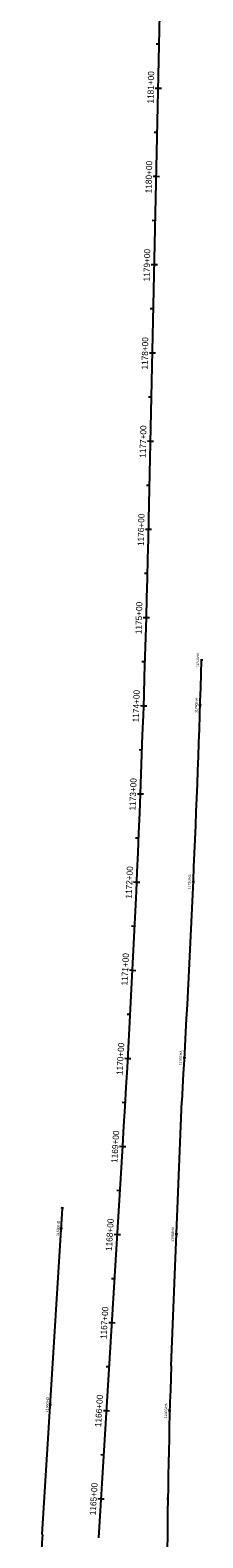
# Model space of a CAD drawing. Extents: x 596008 to 607538, y 326212 to 405053.
# Drawn here: x 604113 to 604309, y 341268 to 342976 of the extents above; entities that cross this region are included whole.
import ezdxf

# ---------------------------------------------------------------- set-up
doc = ezdxf.new("R2010")
doc.units = 0
for name, color, linetype in [('P_ALI_200', 7, 'Continuous'), ('P_ALI_200_Sta', 7, 'Continuous'), ('P_ALI_200_Tic', 7, 'Continuous')]:
    doc.layers.add(name, color=color, linetype=linetype)

msp = doc.modelspace()

# ---------------------------------------------------------------- linework, layer by layer
at = {"layer": 'P_ALI_200'}
for points in [[(604247.6, 342421.3), (604296.1, 344641.5)], [(604272.9, 341462.5), (604285.2, 341762.3)], [(604190.8, 341267.5), (604218.1, 341711.8)], [(604126.9, 341271.4), (604149.6, 341641.2)]]:
    msp.add_lwpolyline(points, dxfattribs=at)
for centre, radius, start, end in [((586251.9, 342814.3), 18000, 356.48854, 358.74902), ((586251.9, 342814.3), 18064, 356.66136, 358.24837), ((612353.2, 341187.1), 8085, 178.04799, 179.61083), ((614687.1, 340623.4), 10580, 176.48854, 178.06311)]:
    msp.add_arc(centre, radius, start, end, dxfattribs=at)
at = {"layer": 'P_ALI_200_Sta'}
for points in [[(604259.3, 342959.9), (604255.8, 342960)], [(604258.3, 342909.9), (604254.8, 342910)], [(604258.3, 342909.9), (604258.3, 342909.9)], [(604261.8, 342909.9), (604258.3, 342909.9)], [(604257.2, 342859.9), (604253.7, 342860)], [(604256.1, 342810), (604252.6, 342810)], [(604256.1, 342810), (604256.1, 342810)], [(604259.6, 342809.9), (604256.1, 342810)], [(604255, 342760), (604251.5, 342760.1)], [(604253.9, 342710), (604250.4, 342710.1)], [(604253.9, 342710), (604253.9, 342710)], [(604257.4, 342709.9), (604253.9, 342710)], [(604252.8, 342660), (604249.3, 342660.1)], [(604251.7, 342610), (604248.2, 342610.1)], [(604251.7, 342610), (604251.7, 342610)], [(604255.2, 342609.9), (604251.7, 342610)], [(604250.6, 342560), (604247.1, 342560.1)], [(604249.5, 342510), (604246, 342510.1)], [(604249.5, 342510), (604249.5, 342510)], [(604253, 342510), (604249.5, 342510)], [(604248.4, 342460), (604244.9, 342460.1)], [(604247.3, 342410.1), (604243.8, 342410.1)], [(604247.3, 342410.1), (604247.3, 342410.1)], [(604250.8, 342410), (604247.3, 342410.1)], [(604246.1, 342360.1), (604242.6, 342360.2)], [(604244.8, 342310.1), (604241.3, 342310.2)], [(604244.8, 342310.1), (604244.8, 342310.1)], [(604248.3, 342310), (604244.8, 342310.1)], [(604243.3, 342260.1), (604239.8, 342260.2)], [(604307.4, 342262.2), (604306, 342262.2)], [(604307.4, 342262.2), (604307.4, 342262.2)], [(604308.8, 342262.1), (604307.4, 342262.2)], [(604241.7, 342210.1), (604238.2, 342210.3)], [(604241.7, 342210.1), (604241.7, 342210.1)], [(604245.2, 342210), (604241.7, 342210.1)], [(604305.8, 342210.9), (604304.4, 342210.9)], [(604305.8, 342210.9), (604305.8, 342210.9)], [(604307.2, 342210.8), (604305.8, 342210.9)], [(604240, 342160.2), (604236.5, 342160.3)], [(604238.1, 342110.2), (604234.6, 342110.3)], [(604238.1, 342110.2), (604238.1, 342110.2)], [(604241.6, 342110.1), (604238.1, 342110.2)], [(604236.1, 342060.2), (604232.6, 342060.4)], [(604233.9, 342010.3), (604230.4, 342010.4)], [(604233.9, 342010.3), (604233.9, 342010.3)], [(604237.4, 342010.1), (604233.9, 342010.3)], [(604298, 342011), (604296.6, 342011.1)], [(604298, 342011), (604298, 342011)], [(604299.4, 342011), (604298, 342011)], [(604231.6, 341960.3), (604228.1, 341960.5)], [(604229.2, 341910.4), (604225.7, 341910.6)], [(604229.2, 341910.4), (604229.2, 341910.4)], [(604232.7, 341910.2), (604229.2, 341910.4)], [(604226.6, 341860.5), (604223.1, 341860.7)], [(604223.9, 341810.5), (604220.4, 341810.7)], [(604223.9, 341810.5), (604223.9, 341810.5)], [(604227.4, 341810.3), (604223.9, 341810.5)], [(604288, 341811.3), (604286.6, 341811.3)], [(604288, 341811.3), (604288, 341811.3)], [(604289.4, 341811.2), (604288, 341811.3)], [(604221, 341760.6), (604217.5, 341760.8)], [(604218, 341710.7), (604214.5, 341710.9)], [(604218, 341710.7), (604218, 341710.7)], [(604221.5, 341710.5), (604218, 341710.7)], [(604214.9, 341660.8), (604211.5, 341661)], [(604149.6, 341641.2), (604148.2, 341641.3)], [(604149.6, 341641.2), (604149.6, 341641.2)], [(604151, 341641.1), (604149.6, 341641.2)], [(604148.2, 341618), (604146.8, 341618.1)], [(604148.2, 341618), (604148.2, 341618)], [(604149.6, 341617.9), (604148.2, 341618)], [(604211.9, 341610.9), (604208.4, 341611.1)], [(604211.9, 341610.9), (604211.9, 341610.9)], [(604215.4, 341610.7), (604211.9, 341610.9)], [(604279, 341611.5), (604277.6, 341611.5)], [(604279, 341611.5), (604279, 341611.5)], [(604280.4, 341611.4), (604279, 341611.5)], [(604208.8, 341561), (604205.3, 341561.2)], [(604205.8, 341511.1), (604202.3, 341511.3)], [(604205.8, 341511.1), (604205.8, 341511.1)], [(604209.3, 341510.9), (604205.8, 341511.1)], [(604202.7, 341461.2), (604199.2, 341461.4)], [(604135.9, 341418.4), (604134.6, 341418.5)], [(604135.9, 341418.4), (604135.9, 341418.4)], [(604137.3, 341418.3), (604135.9, 341418.4)], [(604199.6, 341411.3), (604196.1, 341411.5)], [(604199.6, 341411.3), (604199.6, 341411.3)], [(604203.1, 341411.1), (604199.6, 341411.3)], [(604271.3, 341411.6), (604269.9, 341411.7)], [(604271.3, 341411.6), (604271.3, 341411.6)], [(604272.7, 341411.6), (604271.3, 341411.6)], [(604196.6, 341361.4), (604193.1, 341361.6)], [(604193.5, 341311.5), (604190, 341311.7)], [(604193.5, 341311.5), (604193.5, 341311.5)], [(604197, 341311.3), (604193.5, 341311.5)]]:
    msp.add_lwpolyline(points, dxfattribs=at)
at = {"layer": 'P_ALI_200_Tic'}
for points in [[(604302.2, 342110.9), (604301.2, 342111)], [(604293.3, 341911.1), (604292.3, 341911.2)], [(604283.1, 341711.4), (604282.1, 341711.4)], [(604142.1, 341518.2), (604141.1, 341518.2)], [(604274.9, 341511.6), (604273.9, 341511.6)], [(604129.8, 341318.6), (604128.8, 341318.6)], [(604269.2, 341311.6), (604268.2, 341311.7)]]:
    msp.add_lwpolyline(points, dxfattribs=at)

# ---------------------------------------------------------------- texts
at = {"layer": 'P_ALI_200_Sta'}
for s, height, rotation, p in [('1181+00', 7, 88.749, (604252.9, 342892.7)), ('1180+00', 7, 88.749, (604250.7, 342791)), ('1179+00', 7, 88.749, (604248.5, 342691.2)), ('1178+00', 7, 88.749, (604246.3, 342591.3)), ('1177+00', 7, 88.749, (604244.1, 342491.3)), ('1176+00', 7, 88.7131, (604241.9, 342391.4)), ('1175+00', 7, 88.3948, (604239.3, 342291.4)), ('1174GHA', 2.8, 88.2484, (604304.2, 342253.5)), ('1174+00', 7, 88.0765, (604236.1, 342191.5)), ('1174GHA', 2.8, 88.0856, (604302.5, 342202.2)), ('1173+00', 7, 87.7582, (604232.4, 342091.6)), ('1172+00', 7, 87.4399, (604228.1, 341991.7)), ('1172GHA', 2.8, 87.4512, (604294.6, 342002.4)), ('1171+00', 7, 87.1216, (604223.3, 341893.3)), ('1170+00', 7, 86.8032, (604217.8, 341791.8)), ('1170GHA', 2.8, 86.8169, (604284.5, 341802.7)), ('1169+00', 7, 86.4885, (604211.9, 341692.2)), ('1168GHD', 0.00000000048, 86.4885, (604147.6, 341641.3)), ('1168GHD', 2.8, 86.4885, (604145.7, 341609.5)), ('1168+00', 7, 86.4885, (604205.7, 341592.4)), ('1168GHA', 2.8, 87.6489, (604275.7, 341602.9)), ('1167+00', 7, 86.4885, (604199.6, 341492.6)), ('1166GHD', 2.8, 86.4885, (604133.4, 341409.9)), ('1166+00', 7, 86.4885, (604193.5, 341392.8)), ('1166GHA', 2.8, 88.4088, (604268.1, 341403)), ('1165+00', 7, 86.4885, (604187.4, 341293))]:
    msp.add_text(s, height=height, rotation=rotation, dxfattribs=at).set_placement(p)

doc.saveas('drawing.dxf')
